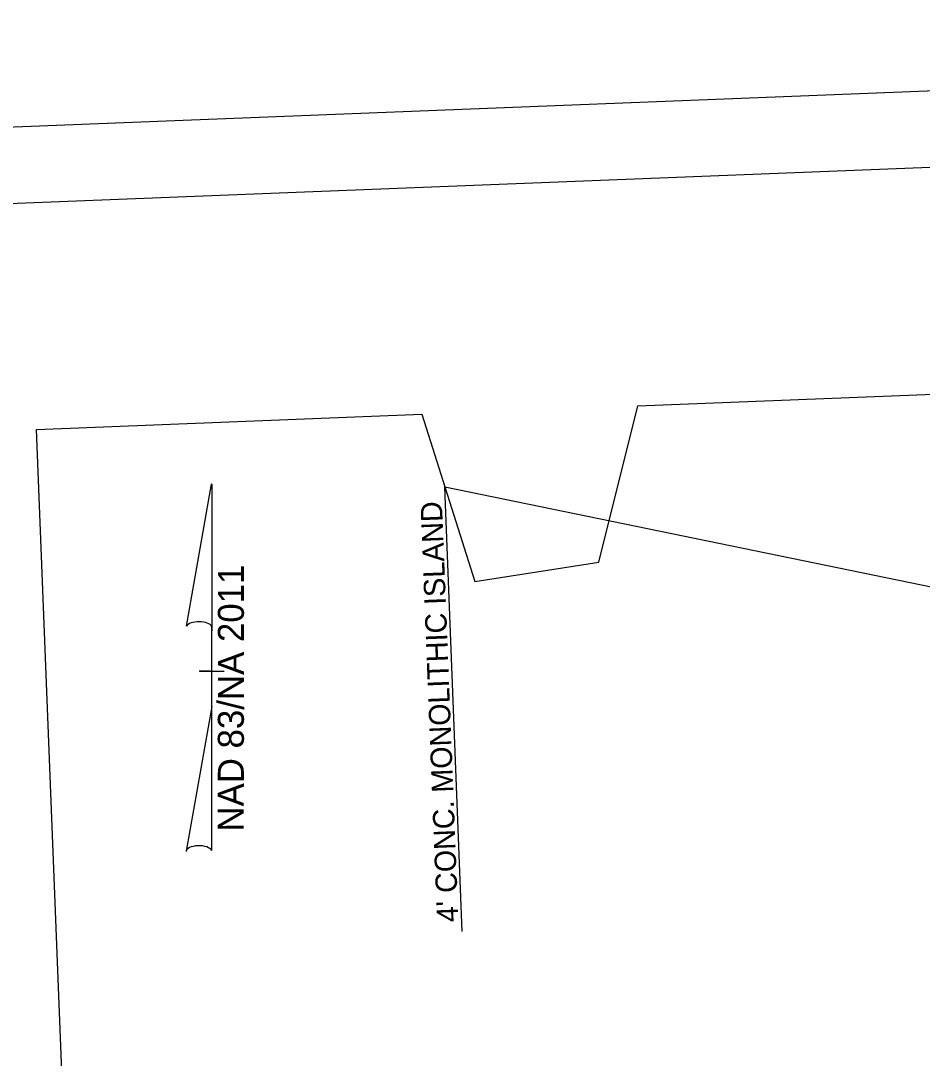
# Model space of a CAD drawing. Extents: x 1627847 to 1629013, y 761524 to 763498.
# Drawn here: x 1628067.6 to 1628362.1, y 762927.1 to 763265.9 of the extents above; entities that cross this region are included whole.
import ezdxf

# ---------------------------------------------------------------- set-up
doc = ezdxf.new("R2010")
doc.units = 0
for name, color, linetype in [('Prop Dimension', 7, 'Continuous'), ('Prop DSN Text', 7, 'Continuous'), ('Prop North Arrow NAD83 for Plan Sheets CELL', 7, 'Continuous'), ('Sheet Clip Boundary CELL', 7, 'Continuous'), ('Sheet Plan And Profile CELL', 7, 'Continuous'), ('Sheet Plot Border Outside CELL', 7, 'Continuous')]:
    doc.layers.add(name, color=color, linetype=linetype)

msp = doc.modelspace()

# ---------------------------------------------------------------- linework, layer by layer
at = {"layer": 'Prop Dimension'}
for p in [(1628211.84, 762968.43), (1628440.23, 763065.41)]:
    msp.add_line(p, (1628206.11, 763113.58), dxfattribs=at)
at = {"layer": 'Prop North Arrow NAD83 for Plan Sheets CELL'}
for p, q in [((1628121.77, 763068.18), (1628129.98, 763114.51)), ((1628130.03, 763114.51), (1628129.98, 763114.51)), ((1628130.03, 763114.51), (1628129.98, 763114.51)), ((1628130.03, 763114.51), (1628130.01, 763066.72)), ((1628130, 763041.93), (1628130.01, 763068.12)), ((1628130.01, 763066.72), (1628130.01, 763068.07)), ((1628126.01, 763053.53), (1628125.96, 763053.53)), ((1628129.56, 763053.53), (1628126.01, 763053.53)), ((1628126.06, 763053.53), (1628134.06, 763053.52)), ((1628130, 763041.93), (1628121.63, 762994.7)), ((1628130.03, 762994.89), (1628130, 763041.93))]:
    msp.add_line(p, q, dxfattribs=at)
for centre, start_param, end_param in [((1628125.9, 763067.68), 0.216388, 2.908219), ((1628125.87, 762994.53), 0.201328, 3.141593)]:
    msp.add_ellipse(centre, major_axis=(4.23, -0.03), ratio=0.461098, start_param=start_param, end_param=end_param, dxfattribs=at)
at = {"layer": 'Sheet Clip Boundary CELL'}
msp.add_lwpolyline([(1628097.28, 762511.58), (1628072.8, 763132.43), (1628198.63, 763137.39), (1628215.93, 763082.79), (1628256.43, 763089.13), (1628269.19, 763140.18), (1628768.96, 763159.88), (1628793.44, 762539.03)], close=True, dxfattribs=at)
at = {"layer": 'Sheet Plan And Profile CELL'}
msp.add_lwpolyline([(1627873.18, 763198.56), (1627932.28, 761699.73), (1628981.47, 761741.1), (1628922.36, 763239.94)], close=True, dxfattribs=at)
at = {"layer": 'Sheet Plot Border Outside CELL'}
msp.add_lwpolyline([(1629013.34, 761567.22), (1628946.36, 763265.9), (1627847.21, 763222.56), (1627914.2, 761523.88)], close=True, dxfattribs=at)

# ---------------------------------------------------------------- texts
at = {"layer": 'Prop DSN Text'}
msp.add_text("4' CONC. MONOLITHIC ISLAND", height=7, rotation=92.2582, dxfattribs=at).set_placement((1628210.61, 762971.64))
at = {"layer": 'Prop North Arrow NAD83 for Plan Sheets CELL'}
msp.add_text('NAD 83/NA 2011', height=8.4975, rotation=89.9757, dxfattribs=at).set_placement((1628140.5, 763001.11))

doc.saveas('drawing.dxf')
